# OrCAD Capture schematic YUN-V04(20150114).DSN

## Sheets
1 Block Diagram: title: Block Diagram; rev: 4; company: dog hunter AG; note: Yun; note: Baarerstrasse 14; note: 6300 Zug
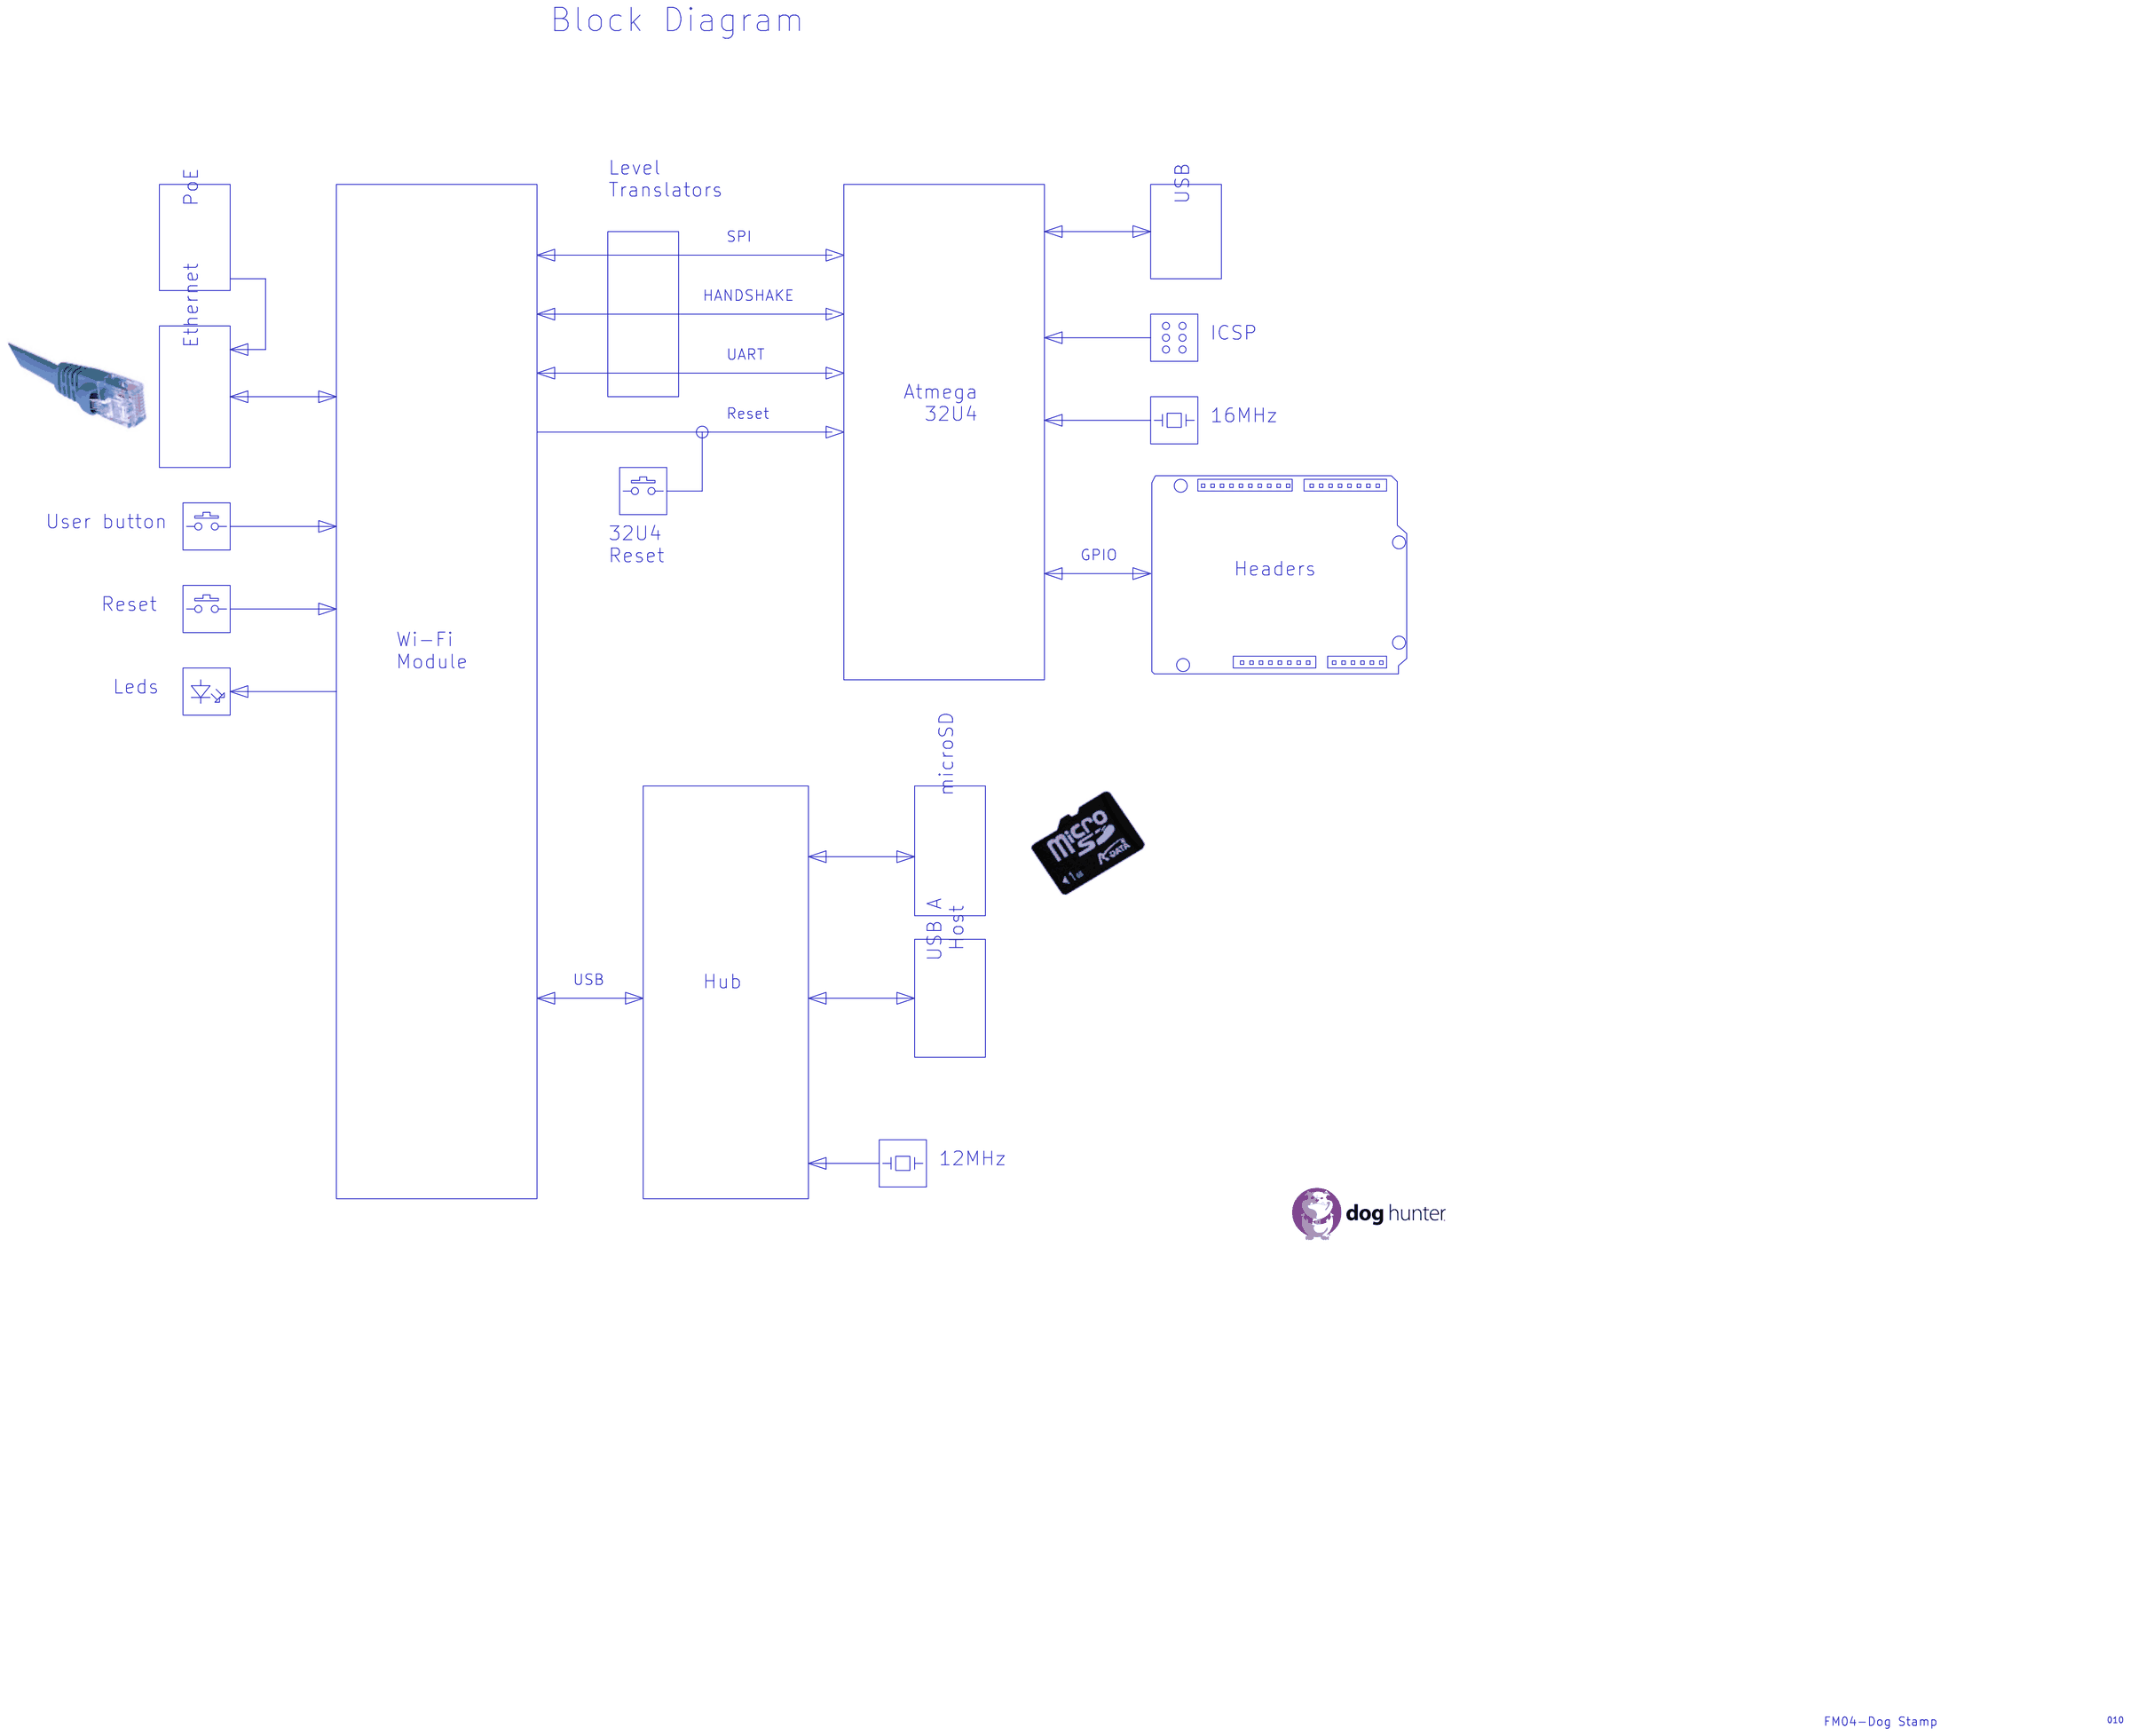
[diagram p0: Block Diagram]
2 Wi-Fi & 32U4: size A3; title: Wi-Fi & 32U4
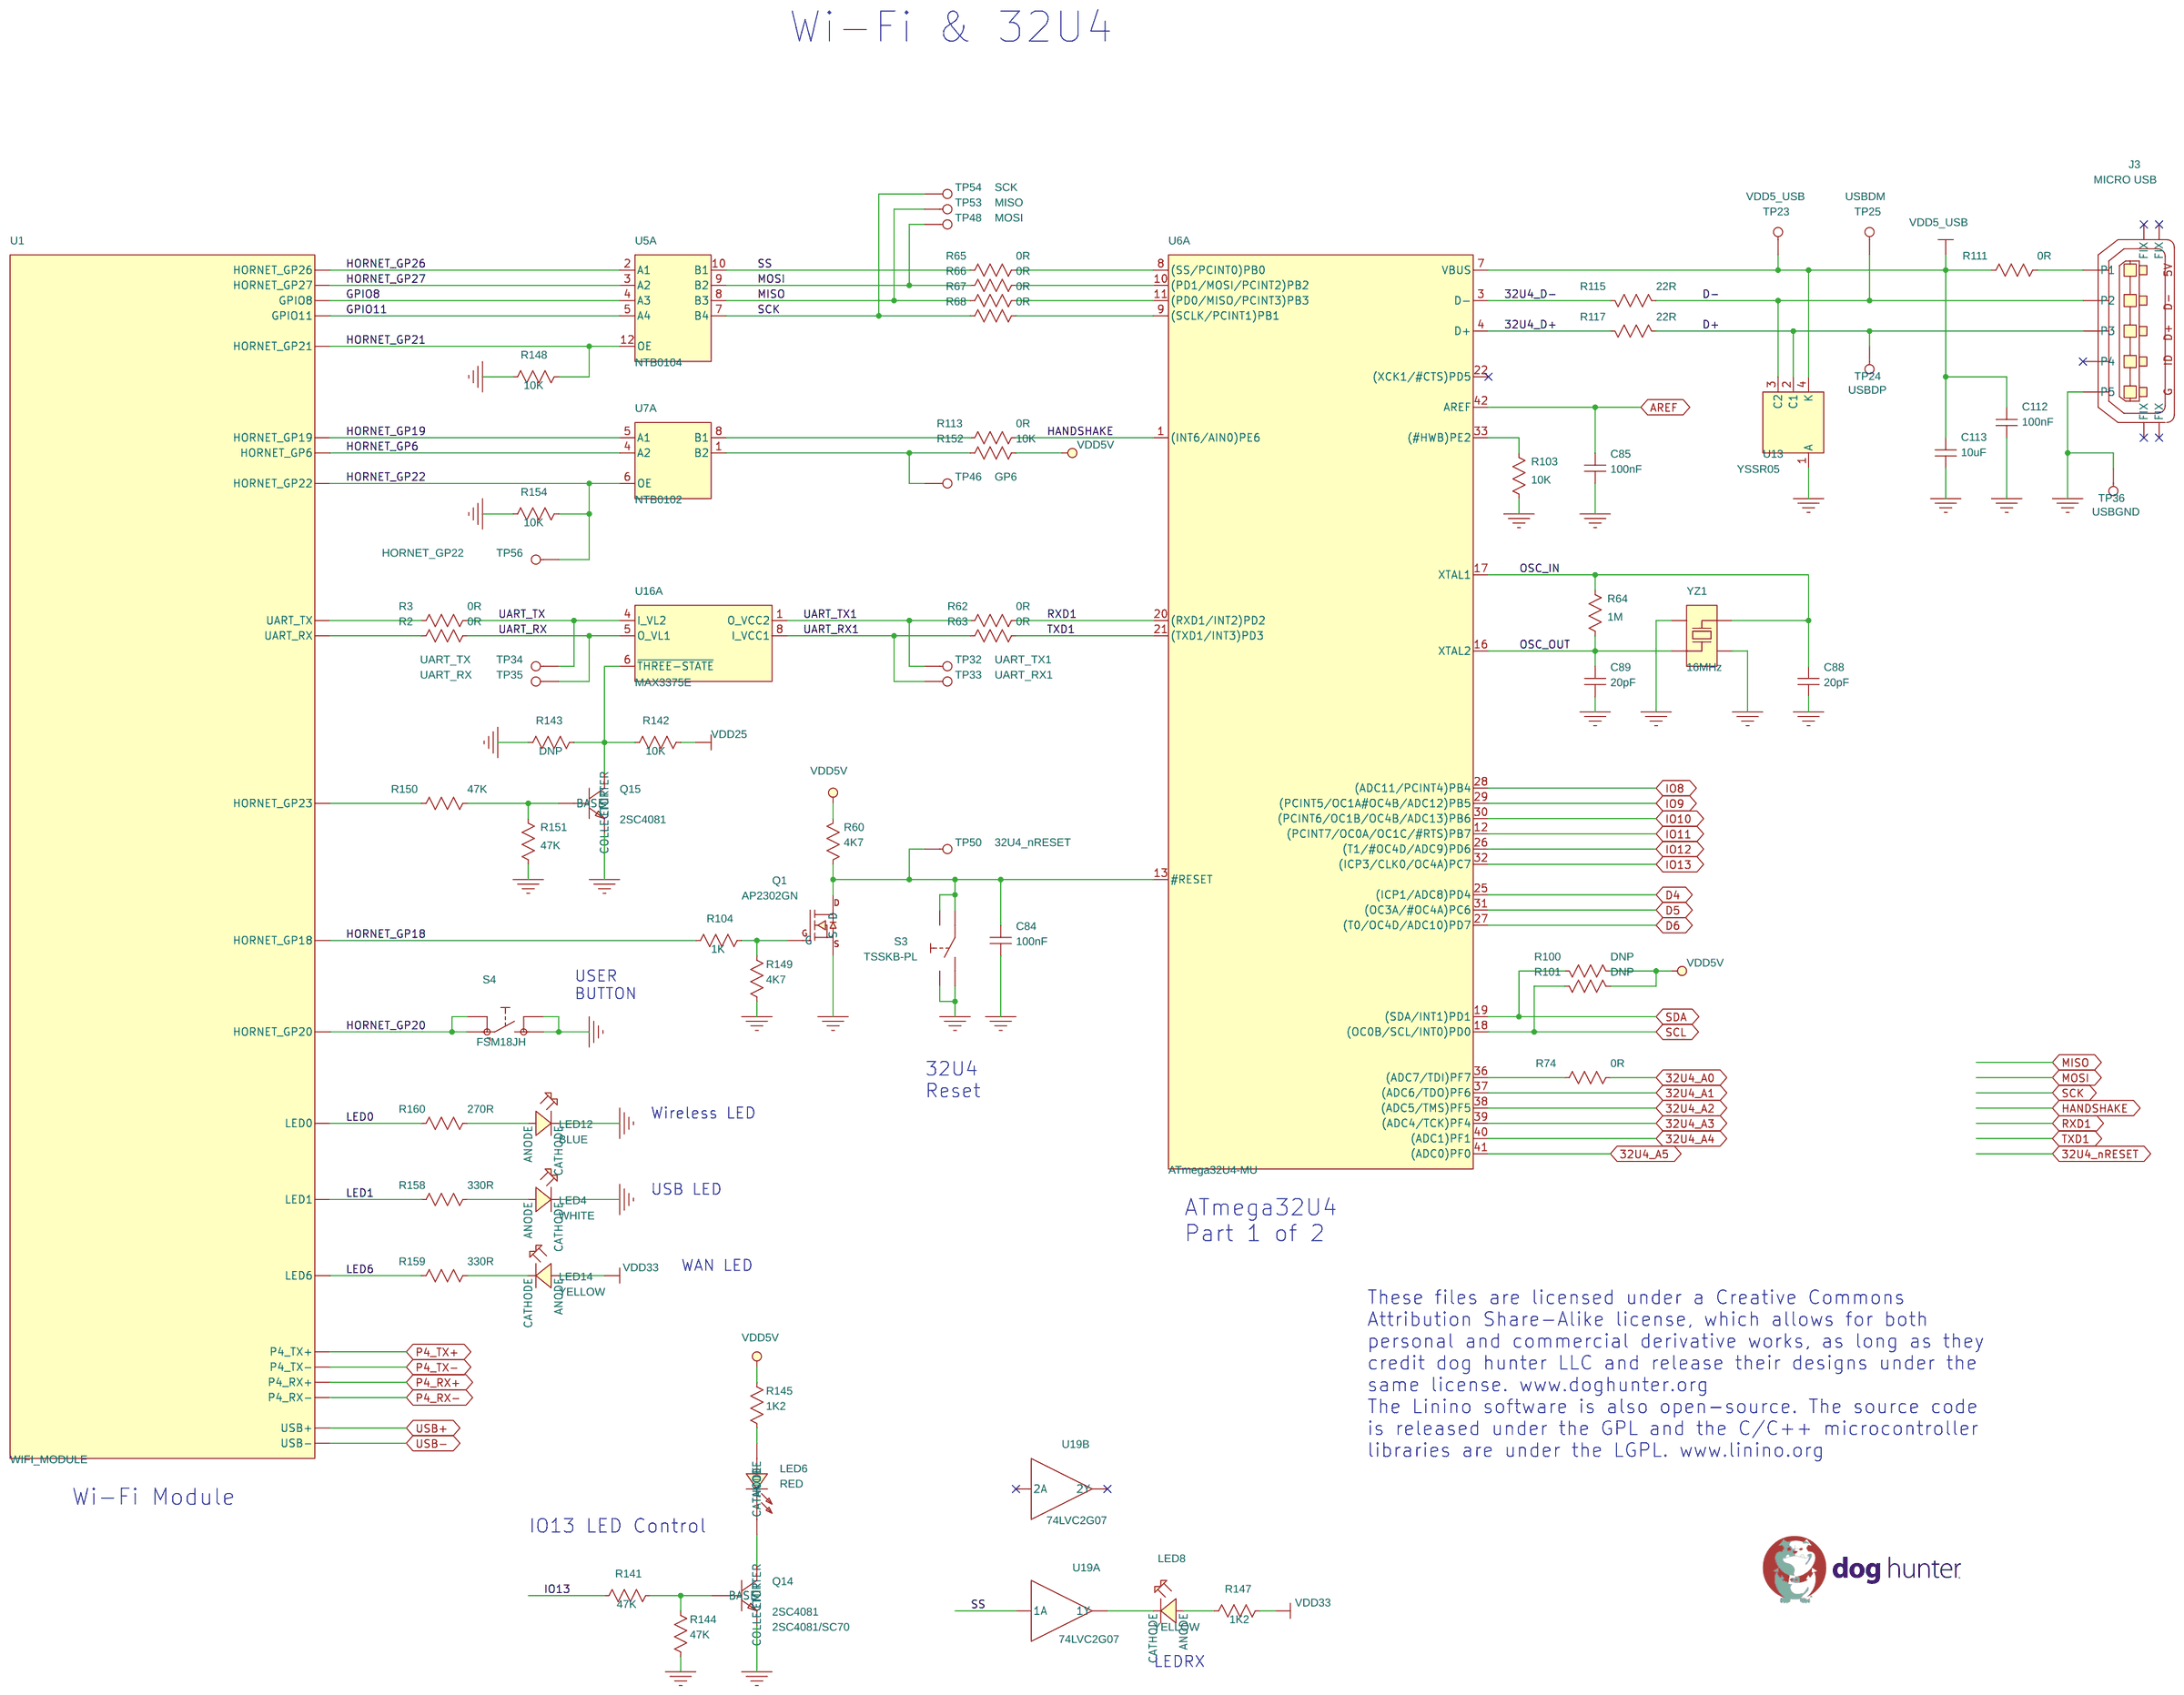
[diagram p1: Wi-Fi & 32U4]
3 Hub, microSD & USB Host: size A3; title: Hub, microSD & USB Host
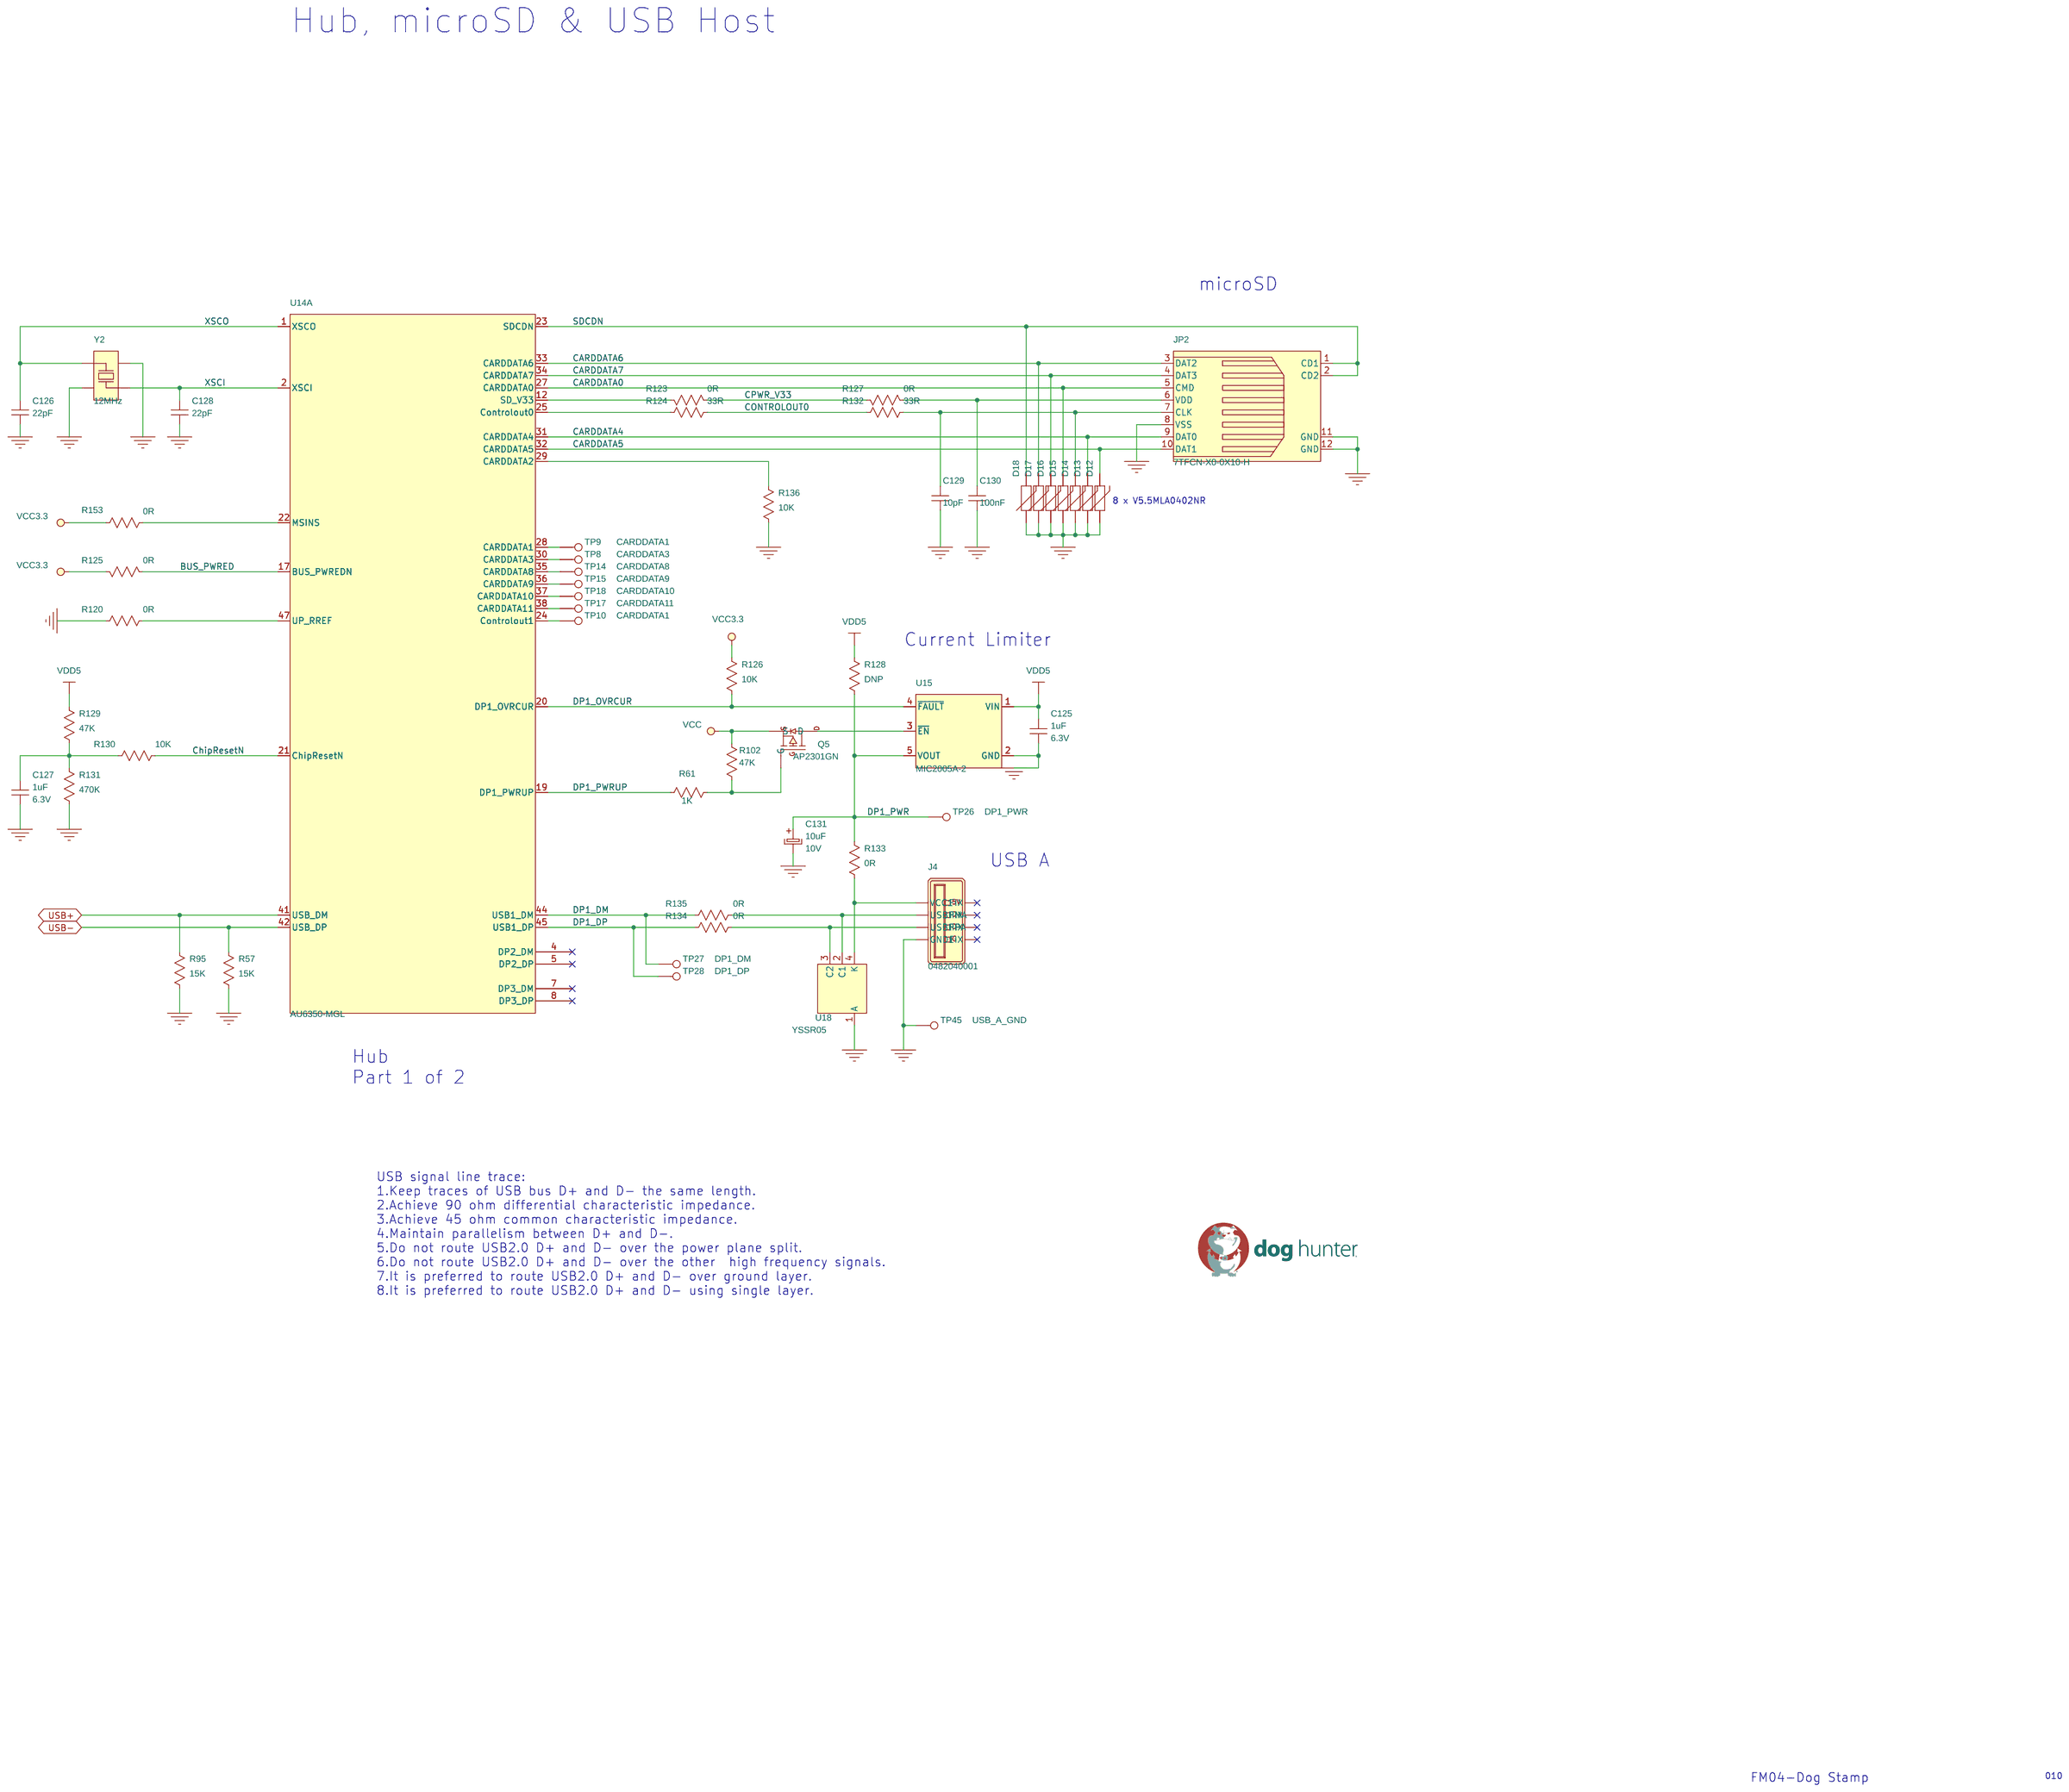
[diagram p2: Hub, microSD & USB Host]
4 Power Supply & Pin Headers: size A3; title: Power Supply & Pin Headers
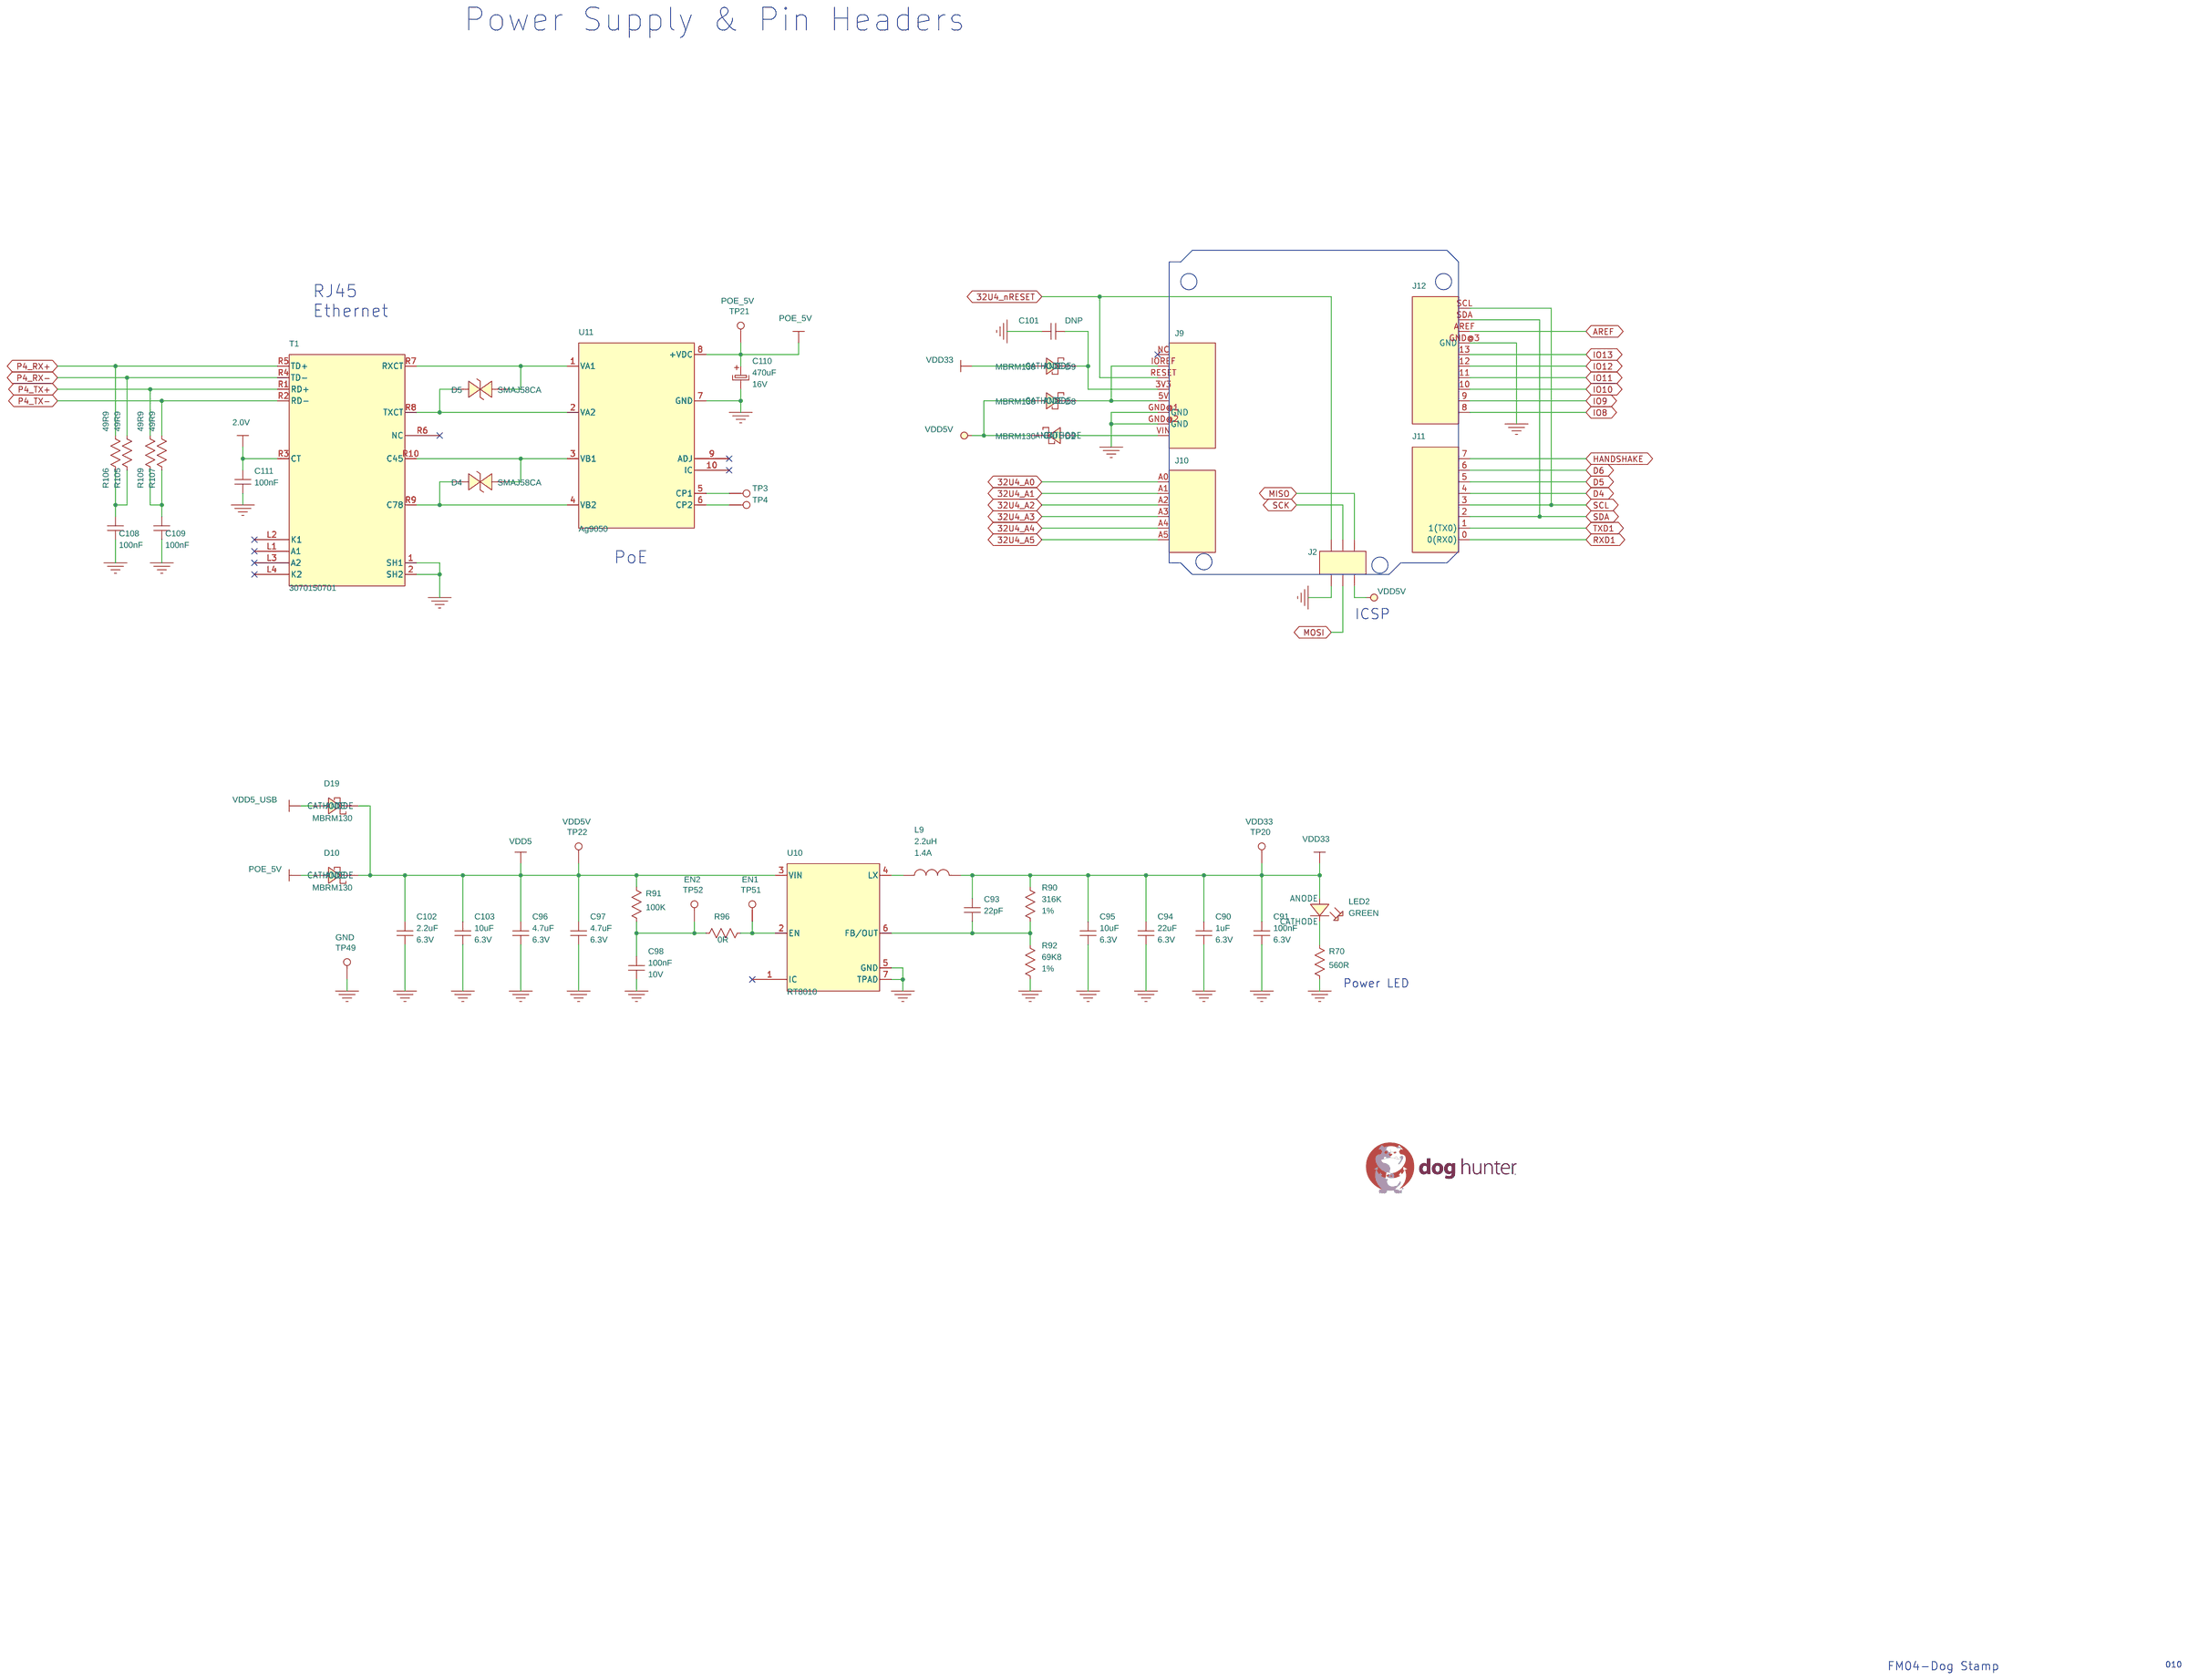
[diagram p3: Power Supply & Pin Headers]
5 IC Power: size Custom; title: IC Power
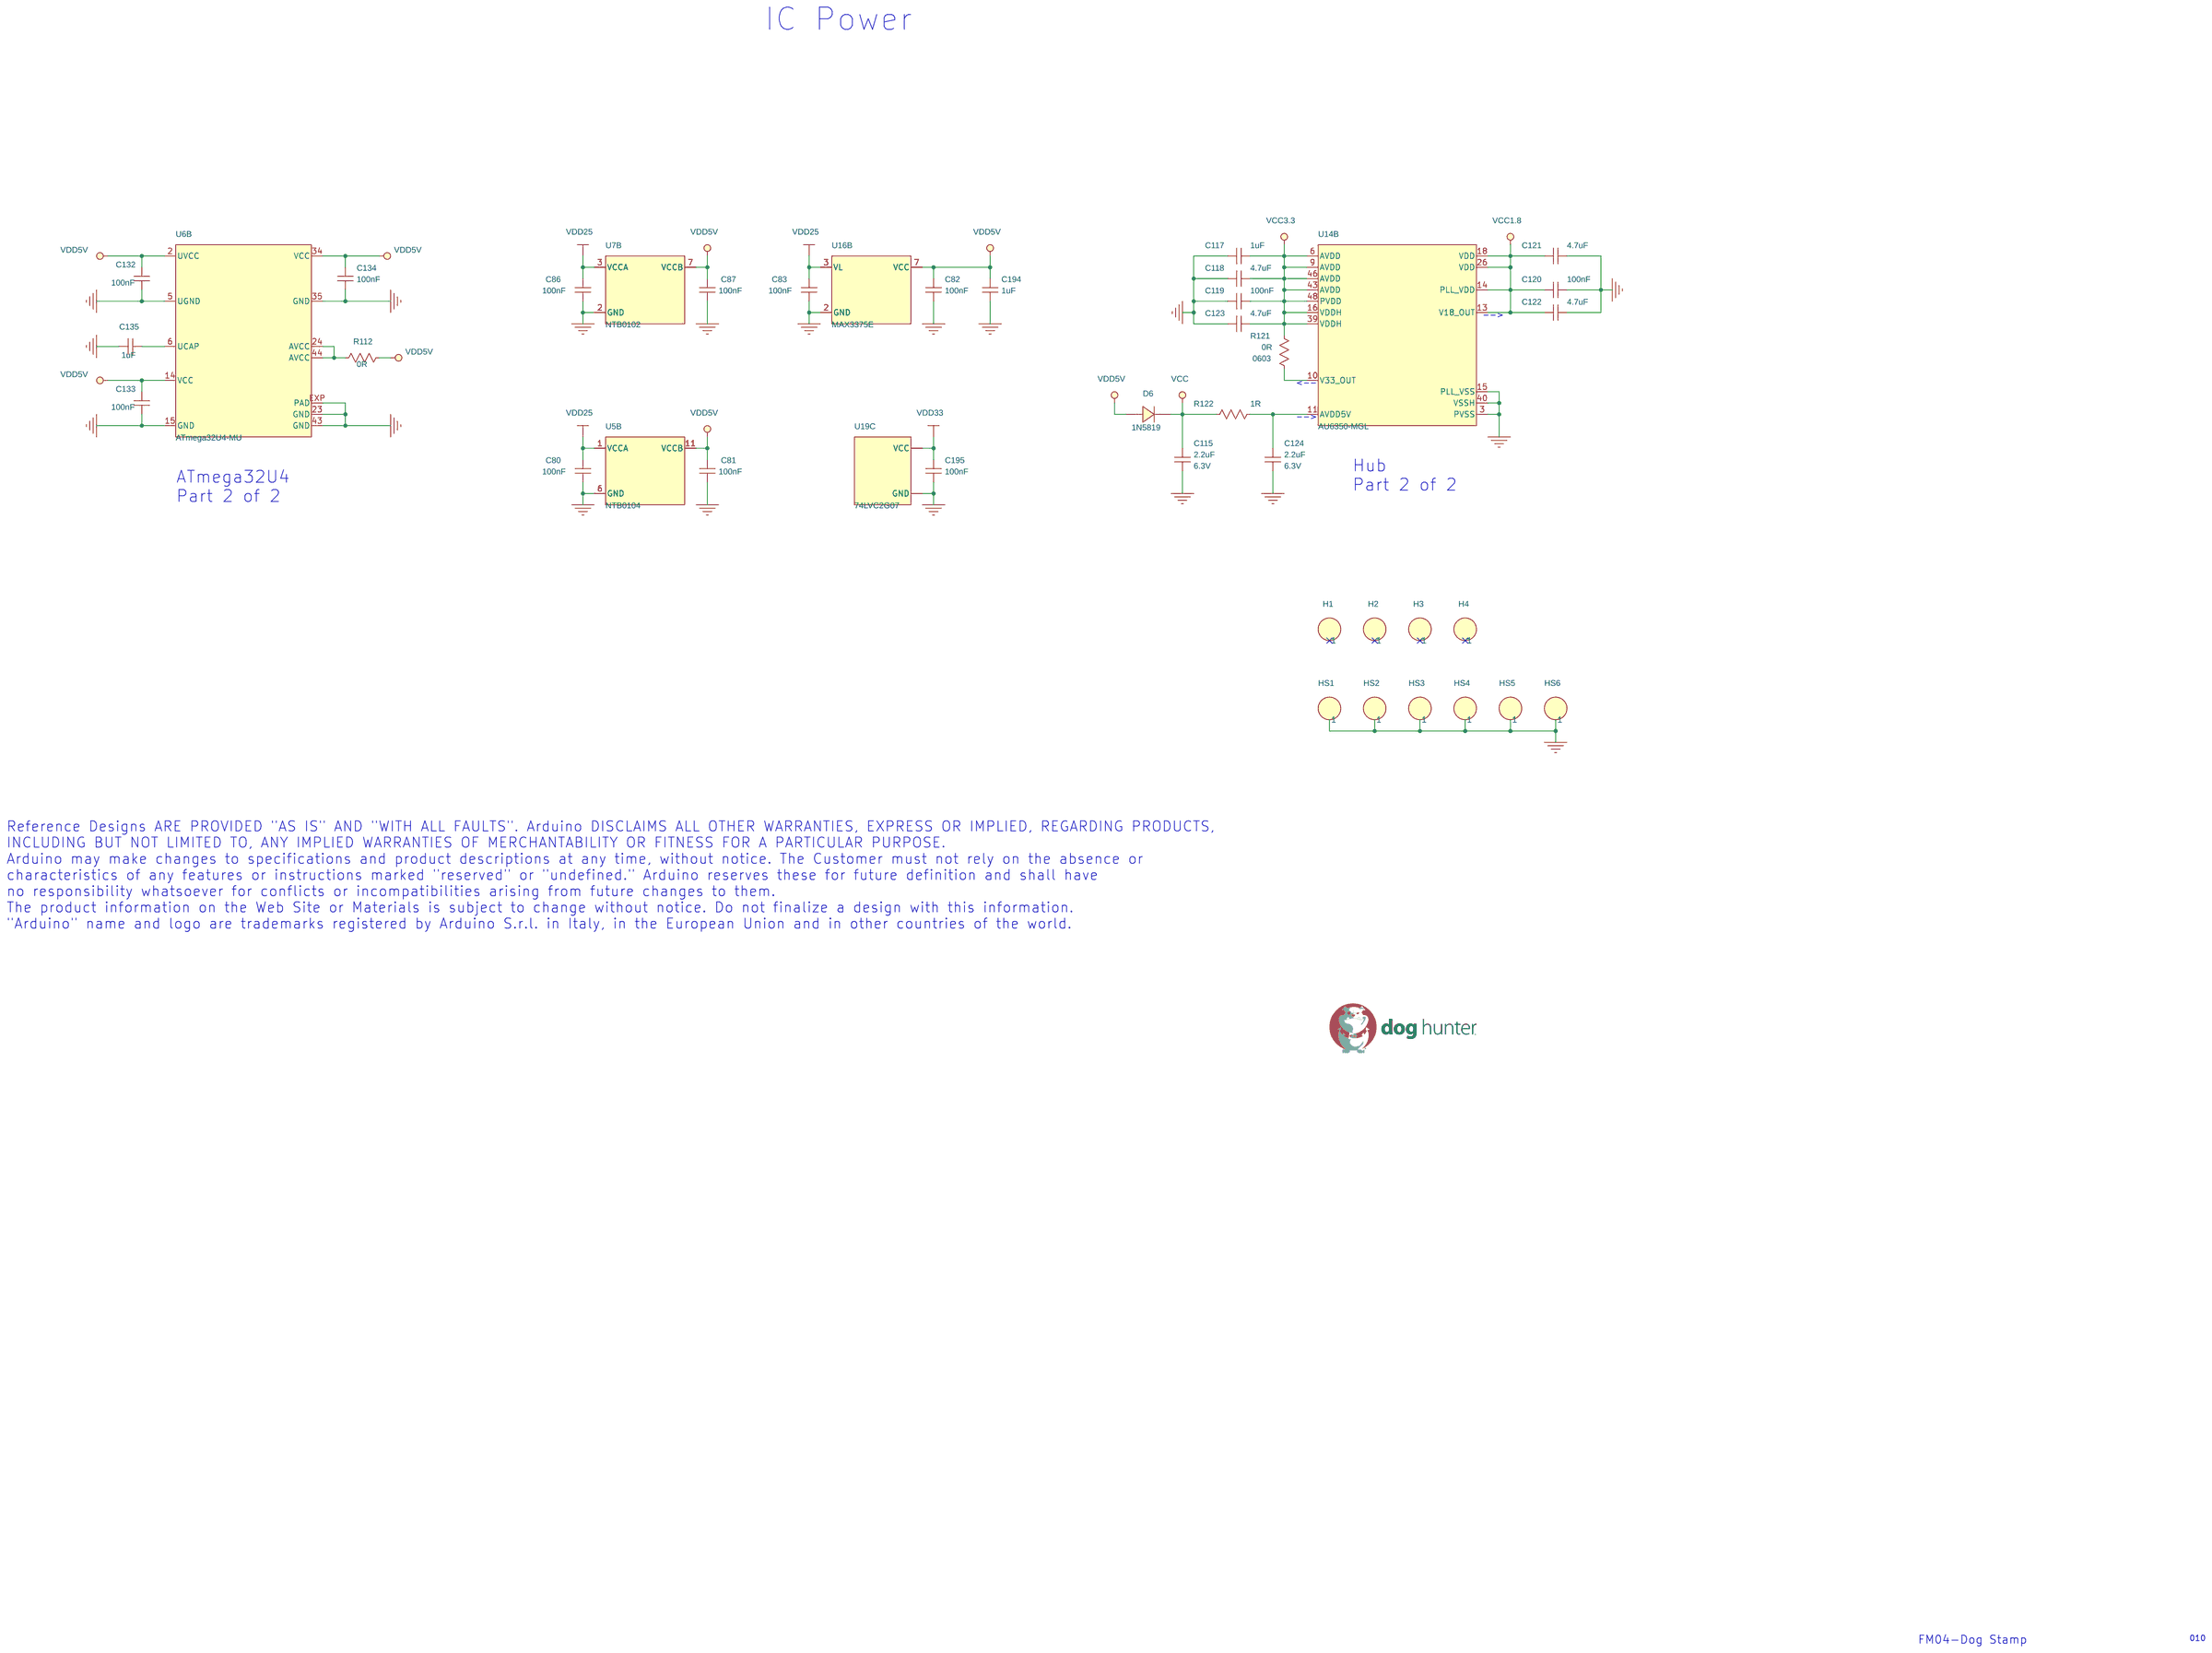
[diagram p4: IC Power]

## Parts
sheet Hub, microSD & USB Host
C125  1uF  [C0402]
C126  22pF  [C0402]
C127  1uF  [C0402]
C128  22pF  [C0402]
C129  10pF  [C0402]
C130  100nF  [C0402]
C131  10uF  [EC\6]
D12  V5.5MLA0402NR  [R0402]
D13  V5.5MLA0402NR  [R0402]
D14  V5.5MLA0402NR  [R0402]
D15  V5.5MLA0402NR  [R0402]
D16  V5.5MLA0402NR  [R0402]
D17  V5.5MLA0402NR  [R0402]
D18  V5.5MLA0402NR  [R0402]
J4  CONN_USB_RT_ANG_RECEPT_TYPE_A  [USB/A-U]
JP2  7TFCN-X0-0X10-H  [SD/MICRO-SD_T-FLASH]
Q5  AP2301GN  [AP2301GN-HF/SOT23]
R57  15K  [R0402]
R61  1K  [R0402]
R95  15K  [R0402]
R102  47K  [R0402]
R120  0R  [R0402]
R123  0R  [R0402]
R124  33R  [R0402]
R125  0R  [R0402]
R126  10K  [R0402]
R127  0R  [R0402]
R128  DNP  [R0402]
R129  47K  [R0402]
R130  10K  [R0402]
R131  470K  [R0402]
R132  33R  [R0402]
R133  0R  [R0402]
R134  0R  [R0402]
R135  0R  [R0402]
R136  10K  [R0402]
R153  0R  [R0402]
TP8  TEST PAD  [PADA]
TP9  TEST PAD  [PADA]
TP10  TEST PAD  [PADA]
TP14  TEST PAD  [PADA]
TP15  TEST PAD  [PADA]
TP17  TEST PAD  [PADA]
TP18  TEST PAD  [PADA]
TP26  TEST PAD  [PADA]
TP27  TEST PAD  [PADA]
TP28  TEST PAD  [PADA]
TP45  TEST PAD  [PADA]
U15  MIC2005A-2  [MIC2005A-2YM5/SOT235]
U18  YSSR05  [YSSR05/SOT-143]
Y2  12MHz  [XTAL/SX5032]
sheet IC Power
C80  100nF  [C0402]
C81  100nF  [C0402]
C82  100nF  [C0402]
C83  100nF  [C0402]
C86  100nF  [C0402]
C87  100nF  [C0402]
C115  2.2uF  [C0402]
C117  1uF  [C0402]
C118  4.7uF  [C0603]
C119  100nF  [C0402]
C120  100nF  [C0402]
C121  4.7uF  [C0603]
C122  4.7uF  [C0603]
C123  4.7uF  [C0603]
C124  2.2uF  [C0402]
C132  100nF  [C0402]
C133  100nF  [C0402]
C134  100nF  [C0402]
C135  1uF  [C0402]
C194  1uF  [C0402]
C195  100nF  [C0402]
D6  1N5819
H1  H2  [PAD1]
H2  H2  [PAD1]
H3  H2  [PAD1]
H4  H2  [PAD1]
HS1  HS1  [HS1]
HS2  HS1  [HS1]
HS3  HS1  [HS1]
HS4  HS1  [HS1]
HS5  HS1  [HS1]
HS6  HS1  [HS1]
R112  0R  [R0201]
R121  0R  [R0603]
R122  1R  [R0603]
U14  AU6350-MGL  [AU6350-MGL/LQFP48-7X7]  (sections A,B)
sheet Power Supply & Pin Headers
C90  1uF  [C0603]
C91  100nF  [C0603]
C93  22pF  [C0402]
C94  22uF  [C0805]
C95  10uF  [C0603]
C96  4.7uF  [C0603]
C97  4.7uF  [C0603]
C98  100nF  [C0603]
C101  DNP  [C0805]
C102  2.2uF  [C0603]
C103  10uF  [C0603]
C108  100nF  [C0402]
C109  100nF  [C0402]
C110  470uF  [EC\6]
C111  100nF  [C0402]
D2  MBRM130  [CASE-457-04]
D4  SMAJ58CA  [D/SMA]
D5  SMAJ58CA  [D/SMA]
D8  MBRM130  [CASE-457-04]
D9  MBRM130  [CASE-457-04]
D10  MBRM130  [CASE-457-04]
D19  MBRM130  [CASE-457-04]
J2  Pitch 2.54 mm  [J100\6D]
J9  PIN HEADER  [PIN-HEADERX4_A]
J10  PIN HEADER  [PIN-HEADERX4_B]
J11  PIN HEADER  [PIN-HEADERX4_C]
J12  PIN HEADER  [PIN-HEADERX4_D]
L9  2.2uH  [L/C3-P1.2R]
LED2  LED_GREEN  [LED0603]
R70  560R  [R0402]
R90  316K  [R0402]
R91  100K  [R0402]
R92  69K8  [R0402]
R96  0R  [R0201]
R105  49R9  [R0402]
R106  49R9  [R0402]
R107  49R9  [R0402]
R109  49R9  [R0402]
T1  RJ45_ETHERNET  [RJ45/RB1-125BHQ1A]
TP3  TEST PAD  [PADA]
TP4  TEST PAD  [PADA]
TP20  TEST PAD  [PADA]
TP21  TEST PAD  [PADA]
TP22  TEST PAD  [PADA]
TP49  TEST PAD  [PADA]
TP51  TEST PAD  [PADA]
TP52  TEST PAD  [PADA]
U10  RT8010  [WDFN-6L-2X2]
U11  Ag9050  [POE/AG9000-S]
sheet Wi-Fi & 32U4
C84  100nF  [C0201]
C85  100nF  [C0402]
C88  20pF  [C0201]
C89  20pF  [C0201]
C112  100nF  [C0402]
C113  10uF  [C0402]
J3  MICRO_USB_5PIN_HORZ_SMD  [USB/MICRO-D03-0718-05002]
LED4  LED_BLUE  [LED0603]
LED6  RED  [LED0603]
LED8  LED_YELLOW  [LED0603]
LED12  LED_BLUE  [LED0603]
LED14  LED_YELLOW  [LED0603]
Q1  AP2302GN  [AP2302GN-HF/SOT23]
Q14  2SC4081  [2SC4081/SC70]
Q15  2SC4081  [2SC4081/SC70]
R2  0R  [R0201]
R3  0R  [R0201]
R60  4K7  [R0201]
R62  0R  [R0201]
R63  0R  [R0201]
R64  1M  [R0201]
R65  0R  [R0201]
R66  0R  [R0201]
R67  0R  [R0201]
R68  0R  [R0201]
R74  0R  [R0201]
R100  DNP  [R0201]
R101  DNP  [R0201]
R103  10K  [R0201]
R104  1K  [R0201]
R111  0R  [R0201]
R113  0R  [R0201]
R115  22R  [R0201]
R117  22R  [R0201]
R141  47K  [R0201]
R142  10K  [R0201]
R143  DNP  [R0201]
R144  47K  [R0201]
R145  1K2  [R0201]
R147  1K2  [R0201]
R148  10K  [R0201]
R149  4K7  [R0201]
R150  47K  [R0201]
R151  47K  [R0201]
R152  10K  [R0201]
R154  10K  [R0201]
R158  330R  [R0402]
R159  330R  [R0402]
R160  270R  [R0402]
S3  TSSKB-PL  [SW/TSSKB]
S4  FSM18JH  [tbd]
TP23  TEST PAD  [PADA]
TP24  TEST PAD  [PADA]
TP25  TEST PAD  [PADA]
TP32  TEST PAD  [PADA]
TP33  TEST PAD  [PADA]
TP34  TEST PAD  [PADA]
TP35  TEST PAD  [PADA]
TP36  TEST PAD  [PADA]
TP46  TEST PAD  [PADA]
TP48  TEST PAD  [PADA]
TP50  TEST PAD  [PADA]
TP53  TEST PAD  [PADA]
TP54  TEST PAD  [PADA]
TP56  TEST PAD  [PADA]
U1  WIFI_MODULE  [QFN-DR-148-EP-2]
U5  NTB0104  [NTB0104/SOT1174]  (sections A,B)
U6  ATmega32U4-MU  [ATMEGA32U4/QFN44]  (sections A,B)
U7  NTB0102  [NTB0102GF/SOT1089]  (sections A,B)
U13  YSSR05  [YSSR05/SOT-143]
U16  MAX3375E  (sections A,B)
U19  74LVC2G07  [SC706]  (sections A,B,C)
YZ1  16MHz  [XTAL/SX5032]

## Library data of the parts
C85 C112 C113 C115 C124 C125 = CAP_NP: CAP CER 2.2UF 6.3V 20% X5R 0402; Package: 0402; Part Number: CAP_CER_2.2UF_6.3V_20%_X5R_0402; Part Type: Ceramic; Temp Coeff: X5R; Tolerance: 20%; Voltage: 6.3V
C93 C126 C128 = CAP_NP: CAP CER 22PF 50V 5% NP0 0402; Package: 0402; Part Number: CAP_CER_22PF_50V_5%_NP0_0402; Part Type: Ceramic; Temp Coeff: NP0; Tolerance: 5%; Voltage: 50V
C117 C127 = CAP_NP: CAP CER 1UF 6.3V 10% X5R 0402; Package: 0402; Part Number: CAP_CER_1UF_6.3V_10%_X5R_0402; Part Type: Ceramic; Temp Coeff: X5R; Tolerance: 10%; Voltage: 6.3V
C129 = CAP_NP: CAP CER 10PF 50V 5% NP0 0402; Package: 0402; Part Number: CAP_CER_10PF_50V_5%_NP0_0402; Part Type: Ceramic; Temp Coeff: NP0; Tolerance: ±5%; Voltage: 50V
C80-C83 C86 C87 C108 C109 C111 C119 C120 C130 C132-C134 C194 C195 = CAP_NP: CAP CER 0.1UF 16V 10% X7R 0402; Package: 0402; Part Number: CAP_CER_0.1UF_16V_10%_X7R_0402; Part Type: Ceramic; Temp Coeff: X7R; Tolerance: 10%; Voltage: 16V
C131 = CAP_POL: CAP ALUM 120UF 10V 20% SMD; Part Number: CAP_ALUM_120UF_10V_20%_SMD; Part Type: Aluminum; Tolerance: 20%; Voltage: 10V
D12-D18 = VARISTOR: VARISTOR 10.8V 20A 0402; Current: 20A; Package: 0402; Part Type: Varistor; Voltage: 5.5V
J4 = USB_A: CONN USB RT ANG RECEPT TYPE A; DESCR: 0482040001; Part Type: USB/A
JP2 = 7TFCN-X0-0X10-H: CONN MICRO SD SMD; Part Type: microSD
Q5 = MOSFET_P_SOT-23_DH: MOSFET P SOT23 20V 2.6A 130MOHM; Current: 2.6A; Package: SOT-23-3; Part Number: AP2301GN-HF; Part Type: MOSFET P; Voltage: 20V
R57 R95 = R: RES 15K OHM 1/16W 5% 0402 SMD; Package: 0402; Part Number: RES_15K_OHM_1/16W_5%_0402_SMD; Part type: Thick film; Power: 1/16W; Tolerance: 5%
R61 R120 R123 R125 R134-R136 R153 = R: RES 0.0 OHM 1/16W JUMP 0402 SMD; Package: 0402; Part Number: RES_0.0_OHM_1/16W_JUMP_0402_SMD; Part type: Thick film; Power: 1/16W; Tolerance: NA
R91 R102 R126 R128 = R: RES 100K OHM 1/16W 1% 0402 SMD; Package: 0402; Part Number: RES_100K_OHM_1/16W_1%_0402_SMD; Part type: Thick film; Power: 1/16W; Tolerance: 1%
R124 R127 R132 = R: RES 33 OHM 1/16W 5% 0402 SMD; Package: 0402; Part Number: RES_33_OHM_1/16W_5%_0402_SMD; Part type: Thick film; Power: 1/16W; Tolerance: 5%
R129 = R: RES 47.0K OHM 1/16W 1% 0402 SMD; Package: 0402; Part Number: RES_47.0K_OHM_1/16W_1%_0402_SMD; Part type: Thick film; Power: 1/16W; Tolerance: 1%
R130 R133 = R: RES 10K OHM 1/16W 5% 0402 SMD; Package: 0402; Part Number: RES_10K_OHM_1/16W_5%_0402_SMD; Part type: Thick film; Power: 1/16W; Tolerance: 5%
R131 = R: RES 470K OHM 1/16W 1% 0402 SMD; Package: 0402; Part Number: RES_470K_OHM_1/16W_1%_0402_SMD; Part type: Thick film; Power: 1/16W; Tolerance: 1%
TP8 = TEST_PAD: LABEL: CARDDATA3; Part Type: Testpoint
TP9 TP10 = TEST_PAD: LABEL: CARDDATA1; Part Type: Testpoint
TP14 = TEST_PAD: LABEL: CARDDATA8; Part Type: Testpoint
TP15 = TEST_PAD: LABEL: CARDDATA9; Part Type: Testpoint
TP17 = TEST_PAD: LABEL: CARDDATA11; Part Type: Testpoint
TP18 = TEST_PAD: LABEL: CARDDATA10; Part Type: Testpoint
TP26 = TEST_PAD: LABEL: DP1_PWR; Part Type: Testpoint
TP27 = TEST_PAD: LABEL: DP1_DM; Part Type: Testpoint
TP28 = TEST_PAD: LABEL: DP1_DP; Part Type: Testpoint
TP45 = TEST_PAD: LABEL: USB_A_GND; Part Type: Testpoint
U15 = MIC2025A-2_0: IC PWR SWITCH ACTIVE LOW SOT23-5; Package: SOT 23 5; Part Type: Power/Distribution
U13 U18 = YSSR05: TVS DIODE ARRAY; Package: SOT-143; Part Type: TVS Diode Array
Y2 = CRYSTAL_4-SMT_1-3: CRYSTAL 12MHZ 10PF SMD ±20PPM 5.0X3.2; Package: 4-SMD 5.0X3.2; Part Number: CRYSTAL_12MHZ_4-SMD_5.0_3.2; Part Type: Crystal
C96 C97 C102 C103 C118 C121-C123 = CAP_NP: CAP CER 4.7UF 6.3V 10% X5R 0603; Package: 0603; Part Number: CAP_CER_4.7UF_6.3V_10%_X5R_0603; Part Type: Ceramic; Temp Coeff: X5R; Tolerance: 10%; Voltage: 6.3V
C135 = CAP_NP: CAP CER 10000PF 50V 10% X7R 0402; Package: 0402; Part Number: CAP_CER_10000PF_50V_10%_X7R_0402; Part Type: Ceramic; Temp Coeff: X7R; Tolerance: 10%; Voltage: 50V
D6 = DIODE
H1-H4 = PAD: 3.2MM HOLE; Part Type: Hole
HS1-HS6 = PAD: 1.4x0.4MM HOLE; Part Type: Hole
R2 R3 R62 R63 R65-R68 R74 R96 R100 R101 R104 R111-R113 R115 R117 R141-R143 R147 R148 R150 R152 R154 = R: RES 0.0 OHM 1/20W JUMP 0201 SMD; Package: 0201; Part Number: RES_0.0_OHM_1/20W_JUMP_0201_SMD; Part type: Thick film; Power: 1/20W; Tolerance: NA
R121 = R: RES 0.0 OHM 1/10W JUMP 0603 SMD; Package: 0603; Part Number: RES_0.0_OHM_1/10W_JUMP_0603_SMD; Part type: Thick film; Power: 1/10W; Tolerance: NA
R122 = R: RES 1 OHM 1/10W 1% 0603 SMD; Package: 0603; Part Number: RES_1_OHM_1/10W_1%_0603_SMD; Part type: Thick film; Power: 1/10W; Tolerance: 1%
U14 = AU6350-MGL_21: IC USB 2.0 HUB-READER 48PIN; POWER_GROUP: HUB; Package: LQFP 48; Part Type: USB/Hub
C90 C91 C95 = CAP_NP: CAP CER 10UF 6.3V 20% X5R 0603; Package: 0603; Part Number: CAP_CER_10UF_6.3V_20%_X5R_0603; Part Type: Ceramic; Temp Coeff: X5R; Tolerance: 20%; Voltage: 6.3V
C94 C101 = CAP_NP: CAP CER 22UF 6.3V 20% X5R 0805; Package: 0805; Part Number: CAP_CER_22UF_6.3V_20%_X5R_0805; Part Type: Ceramic; Temp Coeff: X5R; Tolerance: 20%; Voltage: 6.3V
C98 = CAP_NP: CAP CER 4.7UF 6.3V 10% X5R 0603; Package: 0603; Part Number: CAP_CER_4.7UF_6.3V_10%_X5R_0603; Part Type: Ceramic; Temp Coeff: X5R; Tolerance: 10%; Voltage: 10V
C110 = CAP_POL: CAP ALUM 470UF 16V 20% PTH RADIAL; Part Number: CAP_ALUM_470UF_16V_20%_PTH_RADIAL; Part Type: Aluminum; Tolerance: 20%; Voltage: 16V
D2 D8-D10 D19 = DIODE_SCHOTTKY: DIODE SCHOTTKY 30V 1A POWERMITE; Current: 1A; Forward Voltage Drop: 380mV a 1A; Package: DO-216AA; Part Number: MBRM130LT1G; Part Type: Schottky; Voltage: 30V
D4 D5 = TVS_BI: TVS BIDIRECT 400W 58V SMA; Package: DO-214AC, SMA; Part Type: TVS Diode Bid; Power: 400W; Voltage: 58V
J2 = CON7_6
J9 = HEADER_9_2
J10 = HEADER_9_3
J11 = HEADER_9_4
J12 = HEADER_9_8
L9 = INDUCTOR: INDUCTOR 2.2uH ±30% 1.4A 3.0X3.0 SMD; Current: 1.4A; Package: 3.0 x 3.0 X 1.2(H); Part Number: IND_2.2UH_1.4A_SMD; Part Type: Power Inductor; Resistance: 90 mOhm; Tolerance: ±30%
LED2 = LED: LED 0603 SMD GREEN; DESCR: GREEN; Package: 0603; Part Number: LED_0603_GREEN; Part Type: Led
R70 = R: RES 560 OHM 1/16W 5% 0402 SMD; Package: 0402; Part Number: RES_560_OHM_1/16W_5%_0402_SMD; Part type: Thick film; Power: 1/16W; Tolerance: 5%
R90 = R: RES 316K OHM 1/16W 1% 0402 SMD; Package: 0402; Part Number: RES_316K_OHM_1/16W_1%_0402_SMD; Part type: Thick film; Power: 1/16W; Tolerance: 1%
R92 = R: RES 69.8K OHM 1/16W 1% 0402 SMD; Package: 0402; Part Number: RES_69.8K_OHM_1/16W_1%_0402_SMD; Part type: Thick film; Power: 1/16W; Tolerance: 1%
R105-R107 R109 = R: RES 49.9 OHM 1/20W 1% 0402 SMD; Package: 0402; Part Number: RES_49.9_OHM_1/20W_1%_0402_SMD; Part type: Thick film; Power: 1/20W; Tolerance: 1%
T1 = RB1-125BHQ1A_3: RJ45 TAB DN w/TRAFO w/LED ETHERNET POE; DESCR: 3070150701; Part Number: RJ45_ETHTRAFO_TABDN_LED; Part Type: Networking
TP3 TP4 = TEST_PAD: Part Type: Testpoint
TP20 = TEST_PAD: LABEL: VDD33; Part Type: Testpoint
TP21 = TEST_PAD: LABEL: POE_5V; Part Type: Testpoint
TP22 = TEST_PAD: LABEL: VDD5V; Part Type: Testpoint
TP49 = TEST_PAD: LABEL: GND; Part Type: Testpoint
TP51 = TEST_PAD: LABEL: EN1; Part Type: Testpoint
TP52 = TEST_PAD: LABEL: EN2; Part Type: Testpoint
U10 = RT8010: IC REG BUCK SYNC 3.3V 1A 6WDFN; Package: WDFN 6; Part Number: RT8010-33GQW; Part Type: Power/Switching
U11 = AG9000_2: PoE MODULE 5V 9W; Part Number: Ag9000; Part Type: PoE
C84 = CAP_NP: CAP CER 0.1UF 6.3V 10% X5R 0201; Package: 0201; Part Number: CAP_CER_0.1UF_6.3V_10%_X5R_0201; Part Type: Ceramic; Temp Coeff: X5R; Tolerance: 10%; Voltage: 6.3V
C88 C89 = CAP_NP: CAP CER 22PF 50V 5% NP0 0201; Package: 0201; Part Number: CAP_CER_22PF_50V_5%_NP0_0201; Part Type: Ceramic; Temp Coeff: NP0; Tolerance: ±5%; Voltage: 50V
J3 = USB_MINI_AB_RECEPTACLE: CONN MICRO USB; DESCR: MICRO USB; HEIGHT: 4.27MM; MFG_NAME01: TE Connectivity Ltd; MFG_PN01: 1734035-2; Part Type: USB/micro; ROHS: Yes
LED4 = LED: LED 0603 SMD BLUE; DESCR: WHITE; Package: 0603; Part Number: LED_0603_BLUE; Part Type: Led
LED6 = LED-0603-LTST-C190GKT_0: AtherosDescription: DIO,LED,GREEN CLEAR,0603,SMD; CISPartType: Diodes\LED
LED8 LED14 = LED: LED 0603 SMD YELLOW; DESCR: YELLOW; Package: 0603; Part Number: LED_0603_YELLOW; Part Type: Led
LED12 = LED: LED 0603 SMD BLUE; DESCR: BLUE; Package: 0603; Part Number: LED_0603_BLUE; Part Type: Led
Q1 = MOSFET_N_SOT-23_DH: MOSFET N SOT23 20V 4.1A 46MOHM; Current: 4.1A; Package: SOT-23-3; Part Number: AP2302GN-HF; Part Type: MOSFET N; Voltage: 20V
Q14 Q15 = NPN_1: BJT NPN;50V;0.15A;SOT-323; Manufacturer: ROHM; yuhwei-footprint: SOT-323
R60 R64 R103 R144 R145 R149 R151 = R: Do Not Place RES 0201; Package: 0201; Part Number: DNP_0201; Part type: DNP; Power: NA; Tolerance: NA
R158 R159 = R: RES 330 OHM 1/16W 5% 0402 SMD; Package: 0402; Part Number: RES_330_OHM_1/16W_5%_0402_SMD; Part type: Thick film; Power: 1/16W; Tolerance: 5%
R160 = R: RES 270 OHM 1/16W 5% 0402 SMD; Package: 0402; Part Number: RES_270_OHM_1/16W_5%_0402_SMD; Part type: Thick film; Power: 1/16W; Tolerance: 5%
S3 = SW_PUSHBUTTON_2: 3.3 X 3.3 Miniature Type Tact Switch; Part Type: Switch/Pushbutton
S4 = SW_PUSHBUTTON_4: SWITCH TACTILE SPST-NO 6.5MM x 4.5MM; Part Type: Switch/Pushbutton
TP23 = TEST_PAD: LABEL: VDD5_USB; Part Type: Testpoint
TP24 = TEST_PAD: LABEL: USBDP; Part Type: Testpoint
TP25 = TEST_PAD: LABEL: USBDM; Part Type: Testpoint
TP32 = TEST_PAD: LABEL: UART_TX1; Part Type: Testpoint
TP33 = TEST_PAD: LABEL: UART_RX1; Part Type: Testpoint
TP34 = TEST_PAD: LABEL: UART_TX; Part Type: Testpoint
TP35 = TEST_PAD: LABEL: UART_RX; Part Type: Testpoint
TP36 = TEST_PAD: LABEL: USBGND; Part Type: Testpoint
TP46 = TEST_PAD: LABEL: GP6; Part Type: Testpoint
TP48 = TEST_PAD: LABEL: MOSI; Part Type: Testpoint
TP50 = TEST_PAD: LABEL: 32U4_nRESET; Part Type: Testpoint
TP53 = TEST_PAD: LABEL: MISO; Part Type: Testpoint
TP54 = TEST_PAD: LABEL: SCK; Part Type: Testpoint
TP56 = TEST_PAD: LABEL: HORNET_GP22; Part Type: Testpoint
U1 = AR9331_66: ATHEROS KEY: 100-90018-000; AtherosDescription: AR9331,HORNET SINGLE CHIP,1X1, 2.4 GHz,802.11N,WLANs,QFN; CISPartType: IC\Atheros
U5 = NTB0104GU12: IC TRANSLATING TXRX 12XQFN; Package: SOT1174-1; Part Type: Logic/Level Translator
U6 = ATmega32U4_8: IC MCU 8BIT 32KB FLASH 44QFN; POWER_GROUP: 32U4; Package: QFN 44; Part Type: CPU/Atmel/megaAVR
U7 = NTB0102GF: TXRX TRANSLATING DUAL 3ST 8XSON; POWER_GROUP: NTB0102-1; Package: SOT1089; Part Type: Logic/Level Translator
U16 = MAX3375E: POWER_GROUP: MAXIM
U19 = 74LVC2G07: IC BUFFER N-INV OP/DRAIN 6TSSOP; POWER_GROUP: G07A; Package: SC 70; Part Number: 74LVC2G07_SC70; Part Type: Logic/Dual-Buffer
YZ1 = CRYSTAL_4-SMT_1-3: CRYSTAL 8MHZ 10PF SMD ±20PPM 5.0X3.2; Package: 4-SMD 5.0X3.2; Part Number: CRYSTAL_8MHZ_4-SMD_5.0_3.2; Part Type: Crystal

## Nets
2.0V: C111.1 T1.R3(CT)
GND: C80.1 C81.1 C82.1 C83.1 C84.2 C85.2 C86.1 C87.1 C88.1 C89.1 C90.1 C91.1 C94.1 C95.1 C96.1 C97.1 C98.1 C101.1 C102.1 C103.1 C108.1 C109.1 C110.2 C111.2 C112.1 C113.1 C115.1 C117.1 C118.1 C119.1 C120.2 C121.2 C122.2 C123.1 C124.1 C125.1 C126.1 C127.1 C128.1 C129.1 C130.1 C131.2 C132.1 C133.1 C134.1 C135.1 C194.1 C195.1 D12.1 D13.1 D14.1 D15.1 D16.1 D17.1 D18.1 HS1.1 HS2.1 HS3.1 HS4.1 HS5.1 HS6.1 J2.6 J3.5(P5) J4.4(GND1) J9.GND@1(GND) J9.GND@2(GND) J12.GND@3(GND) JP2.8(VSS) JP2.11(GND) JP2.12(GND) LED4.2(CATHODE) LED12.2(CATHODE) Q1.3(S) Q14.1(EMITTER) Q15.1(EMITTER) R57.1 R70.1 R92.1 R95.1 R103.1 R120.1 R131.1 R136.1 R143.1 R144.1 R148.1 R149.1 R151.1 R154.1 S3.3 S3.4 S4.2 S4.4 T1.1(SH1) T1.2(SH2) TP36.1 TP45.1 TP49.1 U5.6(GND) U6.5(UGND) U6.15(GND) U6.23(GND) U6.35(GND) U6.43(GND) U6.EXP(PAD) U7.2(GND) U10.5(GND) U10.7(TPAD) U11.7(GND) U13.1(A) U14.3(PVSS) U14.15(PLL_VSS) U14.40(VSSH) U15.2(GND) U16.2(GND) U18.1(A) U19.2(GND) Y2.2 Y2.4 YZ1.2 YZ1.4
VCC: C115.2 D6.1(CATHODE) Q5.3(S) R102.2 R122.1
VCC1.8: C120.1 C121.1 C122.1 U14.13(V18_OUT) U14.14(PLL_VDD) U14.18(VDD) U14.26(VDD)
VCC3.3: C117.2 C118.2 C119.2 C123.2 R121.2 R125.2 R126.2 R153.1 U14.6(AVDD) U14.9(AVDD) U14.16(VDDH) U14.39(VDDH) U14.43(AVDD) U14.46(AVDD) U14.48(PVDD)
VDD5: C96.2 C97.2 C102.2 C103.2 C125.2 D10.C(CATHODE) D19.C(CATHODE) R91.2 R128.2 R129.2 TP22.1 U10.3(VIN) U15.1(VIN)
VDD5_USB: C112.2 C113.2 D19.A(ANODE) R111.1 TP23.1 U6.7(VBUS) U13.4(K)
VDD5V: C81.2 C82.2 C87.2 C132.2 C133.2 C134.2 C194.2 D2.C(CATHODE) D6.2(ANODE) D8.A(ANODE) J2.2 R60.1 R100.1 R101.1 R112.2 R145.2 R152.2 U5.11(VCCB) U6.2(UVCC) U6.14(VCC) U6.34(VCC) U7.7(VCCB) U16.7(VCC)
VDD25: C80.2 C83.2 C86.2 R142.2 U5.1(VCCA) U7.3(VCCA) U16.3(VL)
VDD33: C90.2 C91.2 C93.2 C94.2 C95.2 C195.2 D9.A(ANODE) L9.2 LED2.1(ANODE) LED14.1(ANODE) R90.2 R147.2 TP20.1 U19.5(VCC)
32U4_A0: J10.A0 R74.2
32U4_A1: J10.A1 U6.37((ADC6/TDO)PF6)
32U4_A2: J10.A2 U6.38((ADC5/TMS)PF5)
32U4_A3: J10.A3 U6.39((ADC4/TCK)PF4)
32U4_A4: J10.A4 U6.40((ADC1)PF1)
32U4_A5: J10.A5 U6.41((ADC0)PF0)
32U4_D+: R117.2 U6.4(D+)
32U4_D-: R115.2 U6.3(D-)
32U4_nRESET: J2.5 J9.RESET
AREF: C85.1 J12.AREF U6.42(AREF)
BUS_PWRED: R125.1 U14.17(BUS_PWREDN)
CARDDATA0: D15.2 JP2.5(CMD) U14.27(CARDDATA0)
CARDDATA4: D13.2 JP2.9(DAT0) U14.31(CARDDATA4)
CARDDATA5: D12.2 JP2.10(DAT1) U14.32(CARDDATA5)
CARDDATA6: D17.2 JP2.3(DAT2) U14.33(CARDDATA6)
CARDDATA7: D16.2 JP2.4(DAT3) U14.34(CARDDATA7)
ChipResetN: R130.2 U14.21(ChipResetN)
CONTROLOUT0: R124.2 R132.1
CPWR_V33: R123.1 R127.2
D4: J11.4 U6.25((ICP1/ADC8)PD4)
D5: J11.5 U6.31((OC3A/#OC4A)PC6)
D6: J11.6 U6.27((T0/OC4D/ADC10)PD7)
D+: J3.3(P3) R117.1 TP24.1 U13.2(C1)
D-: J3.2(P2) R115.1 TP25.1 U13.3(C2)
DP1_DM: R135.1 TP27.1 U14.44(USB1_DM)
DP1_DP: R134.1 TP28.1 U14.45(USB1_DP)
DP1_OVRCUR: R126.1 U14.20(DP1_OVRCUR) U15.4(~{FAULT})
DP1_PWR: C131.1 R128.1 R133.2 TP26.1 U15.5(VOUT)
DP1_PWRUP: R61.1 U14.19(DP1_PWRUP)
GPIO8: U1.GPIO8 U5.4(A3)
GPIO11: U1.GPIO11 U5.5(A4)
HANDSHAKE: J11.7 R113.2 U6.1((INT6/AIN0)PE6)
HORNET_GP6: U1.HORNET_GP6 U7.4(A2)
HORNET_GP18: R104.1 U1.HORNET_GP18
HORNET_GP19: U1.HORNET_GP19 U7.5(A1)
HORNET_GP20: S4.1 S4.3 U1.HORNET_GP20
HORNET_GP21: R148.2 U1.HORNET_GP21 U5.12(OE)
HORNET_GP22: R154.2 TP56.1 U1.HORNET_GP22 U7.6(OE)
HORNET_GP26: U1.HORNET_GP26 U5.2(A1)
HORNET_GP27: U1.HORNET_GP27 U5.3(A2)
IO8: J12.8 U6.28((ADC11/PCINT4)PB4)
IO9: J12.9 U6.29((PCINT5/OC1A#OC4B/ADC12)PB5)
IO10: J12.10 U6.30((PCINT6/OC1B/OC4B/ADC13)PB6)
IO11: J12.11 U6.12((PCINT7/OC0A/OC1C/#RTS)PB7)
IO12: J12.12 U6.26((T1/#OC4D/ADC9)PD6)
IO13: J12.13 R141.1 U6.32((ICP3/CLK0/OC4A)PC7)
LED0: R160.1 U1.LED0
LED1: R158.1 U1.LED1
LED6: R159.1 U1.LED6
MISO: J2.1 R67.1 TP53.1 U5.8(B3)
MOSI: J2.4 R66.1 TP48.1 U5.9(B2)
OSC_IN: C88.2 R64.2 U6.17(XTAL1) YZ1.1
OSC_OUT: C89.2 R64.1 U6.16(XTAL2) YZ1.3
P4_RX+: R106.2 T1.R5(TD+) U1.P4_RX+
P4_RX-: R105.2 T1.R4(TD-) U1.P4_RX-
P4_TX+: R109.2 T1.R1(RD+) U1.P4_TX+
P4_TX-: R107.2 T1.R2(RD-) U1.P4_TX-
POE_5V: C110.1 D10.A(ANODE) TP21.1 U11.8(+VDC)
RXD1: J11.0(0(RX0)) R62.2 U6.20((RXD1/INT2)PD2)
SCK: J2.3 R68.1 TP54.1 U5.7(B4)
SCL: J11.3 J12.SCL R101.2 U6.18((OC0B/SCL/INT0)PD0)
SDA: J11.2 J12.SDA R100.2 U6.19((SDA/INT1)PD1)
SDCDN: D18.2 JP2.1(CD1) JP2.2(CD2) U14.23(SDCDN)
SS: R65.1 U5.10(B1) U19.1(1A)
TXD1: J11.1(1(TX0)) R63.2 U6.21((TXD1/INT3)PD3)
UART_RX: R2.2 TP35.1 U16.5(O_VL1)
UART_RX1: R63.1 TP33.1 U16.8(I_VCC1)
UART_TX: R3.2 TP34.1 U16.4(I_VL2)
UART_TX1: R62.1 TP32.1 U16.1(O_VCC2)
USB+: R95.2 U1.USB+ U14.41(USB_DM)
USB-: R57.2 U1.USB- U14.42(USB_DP)
XSCI: C128.2 U14.2(XSCI) Y2.1
XSCO: C126.2 U14.1(XSCO) Y2.3
N30086883: LED8.2(CATHODE) U19.6(1Y)
N30086917: LED8.1(ANODE) R147.1
N30478599: C124.2 R122.2 U14.11(AVDD5V)
N30515360: C130.2 JP2.6(VDD) R127.1
N30516940: R124.1 U14.25(Controlout0)
N30517615: R136.2 U14.29(CARDDATA2)
N30526826: R123.2 U14.12(SD_V33)
N30546177: R120.2 U14.47(UP_RREF)
N30553427: J4.2(USBHMA) R135.2 U18.2(C1)
N30553453: J4.3(USBHPA) R134.2 U18.3(C2)
N30572840: C127.2 R129.1 R130.1 R131.2
N30941823: C84.1 Q1.2(D) R60.2 S3.1 S3.2 TP50.1 U6.13(#RESET)
N30941828: Q1.1(G) R104.2 R149.2
N30942145: Q14.2(BASE) R141.2 R144.2
N30942147: LED6.2(CATHODE) Q14.3(COLLECTOR)
N30942267: R2.1 U1.UART_RX
N30942276: R3.1 U1.UART_TX
N30942323: LED6.1(ANODE) R145.1
N30942459: R113.1 U7.8(B1)
N30943953: R112.1 U6.24(AVCC) U6.44(AVCC)
N30944019: C135.2 U6.6(UCAP)
N30954135: R68.2 U6.9((SCLK/PCINT1)PB1)
N30954163: R67.2 U6.11((PD0/MISO/PCINT3)PB3)
N30954191: R66.2 U6.10((PD1/MOSI/PCINT2)PB2)
N30954206: R65.2 U6.8((SS/PCINT0)PB0)
N30986174: R152.1 TP46.1 U7.1(B2)
N30987169: Q15.3(COLLECTOR) R142.1 R143.2 U16.6(~{THREE-STATE})
N31012454: J3.1(P1) R111.2
N31018297: Q15.2(BASE) R150.2 R151.2
N31018299: R150.1 U1.HORNET_GP23
N31081823: R121.1 U14.10(V33_OUT)
N31082380: R153.2 U14.22(MSINS)
N31094448: J4.1(VCC1) R133.1 U18.4(K)
N31096420: Q5.1(G) R61.2 R102.1
N31096460: Q5.2(D) U15.3(~{EN})
N31124681: TP9.1 U14.28(CARDDATA1)
N31124685: TP8.1 U14.30(CARDDATA3)
N31124689: TP14.1 U14.35(CARDDATA8)
N31124693: TP15.1 U14.36(CARDDATA9)
N31124697: TP18.1 U14.37(CARDDATA10)
N31124701: TP17.1 U14.38(CARDDATA11)
N31124705: TP10.1 U14.24(Controlout1)
N31142054: R74.1 U6.36((ADC7/TDI)PF7)
N31148006: C129.2 D14.2 JP2.7(CLK) R132.2
N31167079: C93.1 R90.1 R92.2 U10.6(FB/OUT)
N31167111: C98.2 R91.1 R96.1 TP52.1
N31167113: L9.1 U10.4(LX)
N31167119: R96.2 TP51.1 U10.2(EN)
N31167155: D2.A(ANODE) J9.VIN
N31167157: D8.C(CATHODE) J9.5V J9.IOREF
N31167167: C101.2 D9.C(CATHODE) J9.3V3
N31167210: D5.1 T1.R8(TXCT) U11.2(VA2)
N31167212: D5.2 T1.R7(RXCT) U11.1(VA1)
N31167214: D4.1 T1.R9(C78) U11.4(VB2)
N31167228: D4.2 T1.R10(C45) U11.3(VB1)
N31167290: C109.2 R107.1 R109.1
N31167294: C108.2 R105.1 R106.1
N31167501: TP4.1 U11.6(CP2)
N31167503: TP3.1 U11.5(CP1)
N31175031: LED12.1(ANODE) R160.2
N31175035: LED14.2(CATHODE) R159.2
N31175039: LED4.1(ANODE) R158.2
N31188681: R103.2 U6.33((#HWB)PE2)
N31195705: LED2.2(CATHODE) R70.2

Not connected (* = marked no-connect by the designer): H1 1*; H2 1*; H3 1*; H4 1*; J3 4(P4)* 6(FIX)* 7(FIX)* 8(FIX)* 9(FIX)*; J4 5(FIX)* 6(FIX)* 7(FIX)* 8(FIX)*; J9 NC*; T1 L1(A1)* L2(K1)* L3(A2)* L4(K2)* R6(NC)*; U6 22((XCK1/#CTS)PD5)*; U10 1(IC)*; U11 9(ADJ)* 10(IC)*; U14 4(DP2_DM)* 5(DP2_DP)* 7(DP3_DM)* 8(DP3_DP)*; U19 3(2A)* 4(2Y)*

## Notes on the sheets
sheet 1
- Block Diagram
- Level
  Translators
- PoE
- USB
- SPI
- HANDSHAKE
- ICSP
- Ethernet
- UART
- Atmega
    32U4
- Reset
- 16MHz
- User button
- 32U4
  Reset
- GPIO
- Headers
- Reset
- Wi-Fi
  Module
- Leds
- microSD
- USB A
   Host
- USB
- Hub
- 12MHz
- FM04-Dog Stamp
- 010
sheet 2
- Wi-Fi & 32U4
- USER
  BUTTON
- 32U4
  Reset
- Wireless LED
- USB LED
- ATmega32U4
  Part 1 of 2
- WAN LED
- These files are licensed under a Creative Commons
  Attribution Share-Alike license, which allows for both
  personal and commercial derivative works, as long as they
  credit dog hunter LLC and release their designs under the
  same license. www.doghunter.org
  The Linino software is also open-source. The source code
  is released under the GPL and the C/C++ microcontroller
  libraries are under the LGPL. www.linino.org
- Wi-Fi Module
- IO13 LED Control
- LEDRX
sheet 3
- Hub, microSD & USB Host
- microSD
- 8 x V5.5MLA0402NR
- Current Limiter
- USB A
- Hub
  Part 1 of 2
- USB signal line trace:
  1.Keep traces of USB bus D+ and D- the same length.
  2.Achieve 90 ohm differential characteristic impedance.
  3.Achieve 45 ohm common characteristic impedance.
  4.Maintain parallelism between D+ and D-.
  5.Do not route USB2.0 D+ and D- over the power plane split.
  6.Do not route USB2.0 D+ and D- over the other  high frequency signals.
  7.It is preferred to route USB2.0 D+ and D- over ground layer.
  8.It is preferred to route USB2.0 D+ and D- using single layer.
- FM04-Dog Stamp
- 010
sheet 4
- Power Supply & Pin Headers
- RJ45
  Ethernet
- PoE
- ICSP
- Power LED
- FM04-Dog Stamp
- 010
sheet 5
- IC Power
- -->
- <--
- -->
- Hub
  Part 2 of 2
- ATmega32U4
  Part 2 of 2
- Reference Designs ARE PROVIDED "AS IS" AND "WITH ALL FAULTS". Arduino DISCLAIMS ALL OTHER WARRANTIES, EXPRESS OR IMPLIED, REGARDING PRODUCTS,
  INCLUDING BUT NOT LIMITED TO, ANY IMPLIED WARRANTIES OF MERCHANTABILITY OR FITNESS FOR A PARTICULAR PURPOSE.
  Arduino may make changes to specifications and product descriptions at any time, without notice. The Customer must not rely on the absence or
  characteristics of any features or instructions marked "reserved" or "undefined." Arduino reserves these for future definition and shall have
  no responsibility whatsoever for conflicts or incompatibilities arising from future changes to them.
  The product information on the Web Site or Materials is subject to change without notice. Do not finalize a design with this information.
  "Arduino" name and logo are trademarks registered by Arduino S.r.l. in Italy, in the European Union and in other countries of the world.
- FM04-Dog Stamp
- 010
